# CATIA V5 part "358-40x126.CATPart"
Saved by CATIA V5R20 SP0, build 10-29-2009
Part number: 358-40X126
Definition: NONE
Nomenclature: 358-40X126
Source: Unknown
Description: 358-40X126
Bounding box of the stored display mesh (mm): x -18 to 108, y -26 to 26, z -26 to 26
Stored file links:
  C:\Users\Utente\Desktop\IO LAVORO\3D X SITO CF\X SITO\PLASTICA\358\358-40x126.CATPart
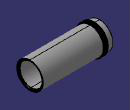
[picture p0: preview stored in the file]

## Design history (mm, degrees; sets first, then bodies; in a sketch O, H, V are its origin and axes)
Body1 "358-40X126" (main body)
  Solid1: solid without history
